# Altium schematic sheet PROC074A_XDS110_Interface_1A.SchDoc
size 431 x 279 mm; Date: Not shown in title block; ApprovedBy: Not shown in title block; CheckedBy: Not shown in title block; Author: Not shown in title block; CompanyName: Not shown in title block; Engineer: Not shown in title block; Organization: Not shown in title block; Address1: Not shown in title block; Address2: Not shown in title block; Address3: Not shown in title block; Address4: Not shown in title block; DocumentNumber: 1; Revision: Use project parameter SCH_Rev; SheetNumber: 11; SheetTotal: 22; PageSetup: Record=PageOptions¦CenterHorizontal=True¦CenterVertical=True¦PrintScale=1.00¦XCorrection=1.00¦YCorrection=1.00¦PrintKind=0¦BorderSize=5000000¦LeftOffset=0¦BottomOffset=0¦Orientation=2¦PaperLength=1000¦PaperWidth=1000¦Scale=100¦PaperSource=15¦PrintQuality=600¦MediaType=1¦DitherType=10¦PaperKind=Letter¦PrintScaleMode=1
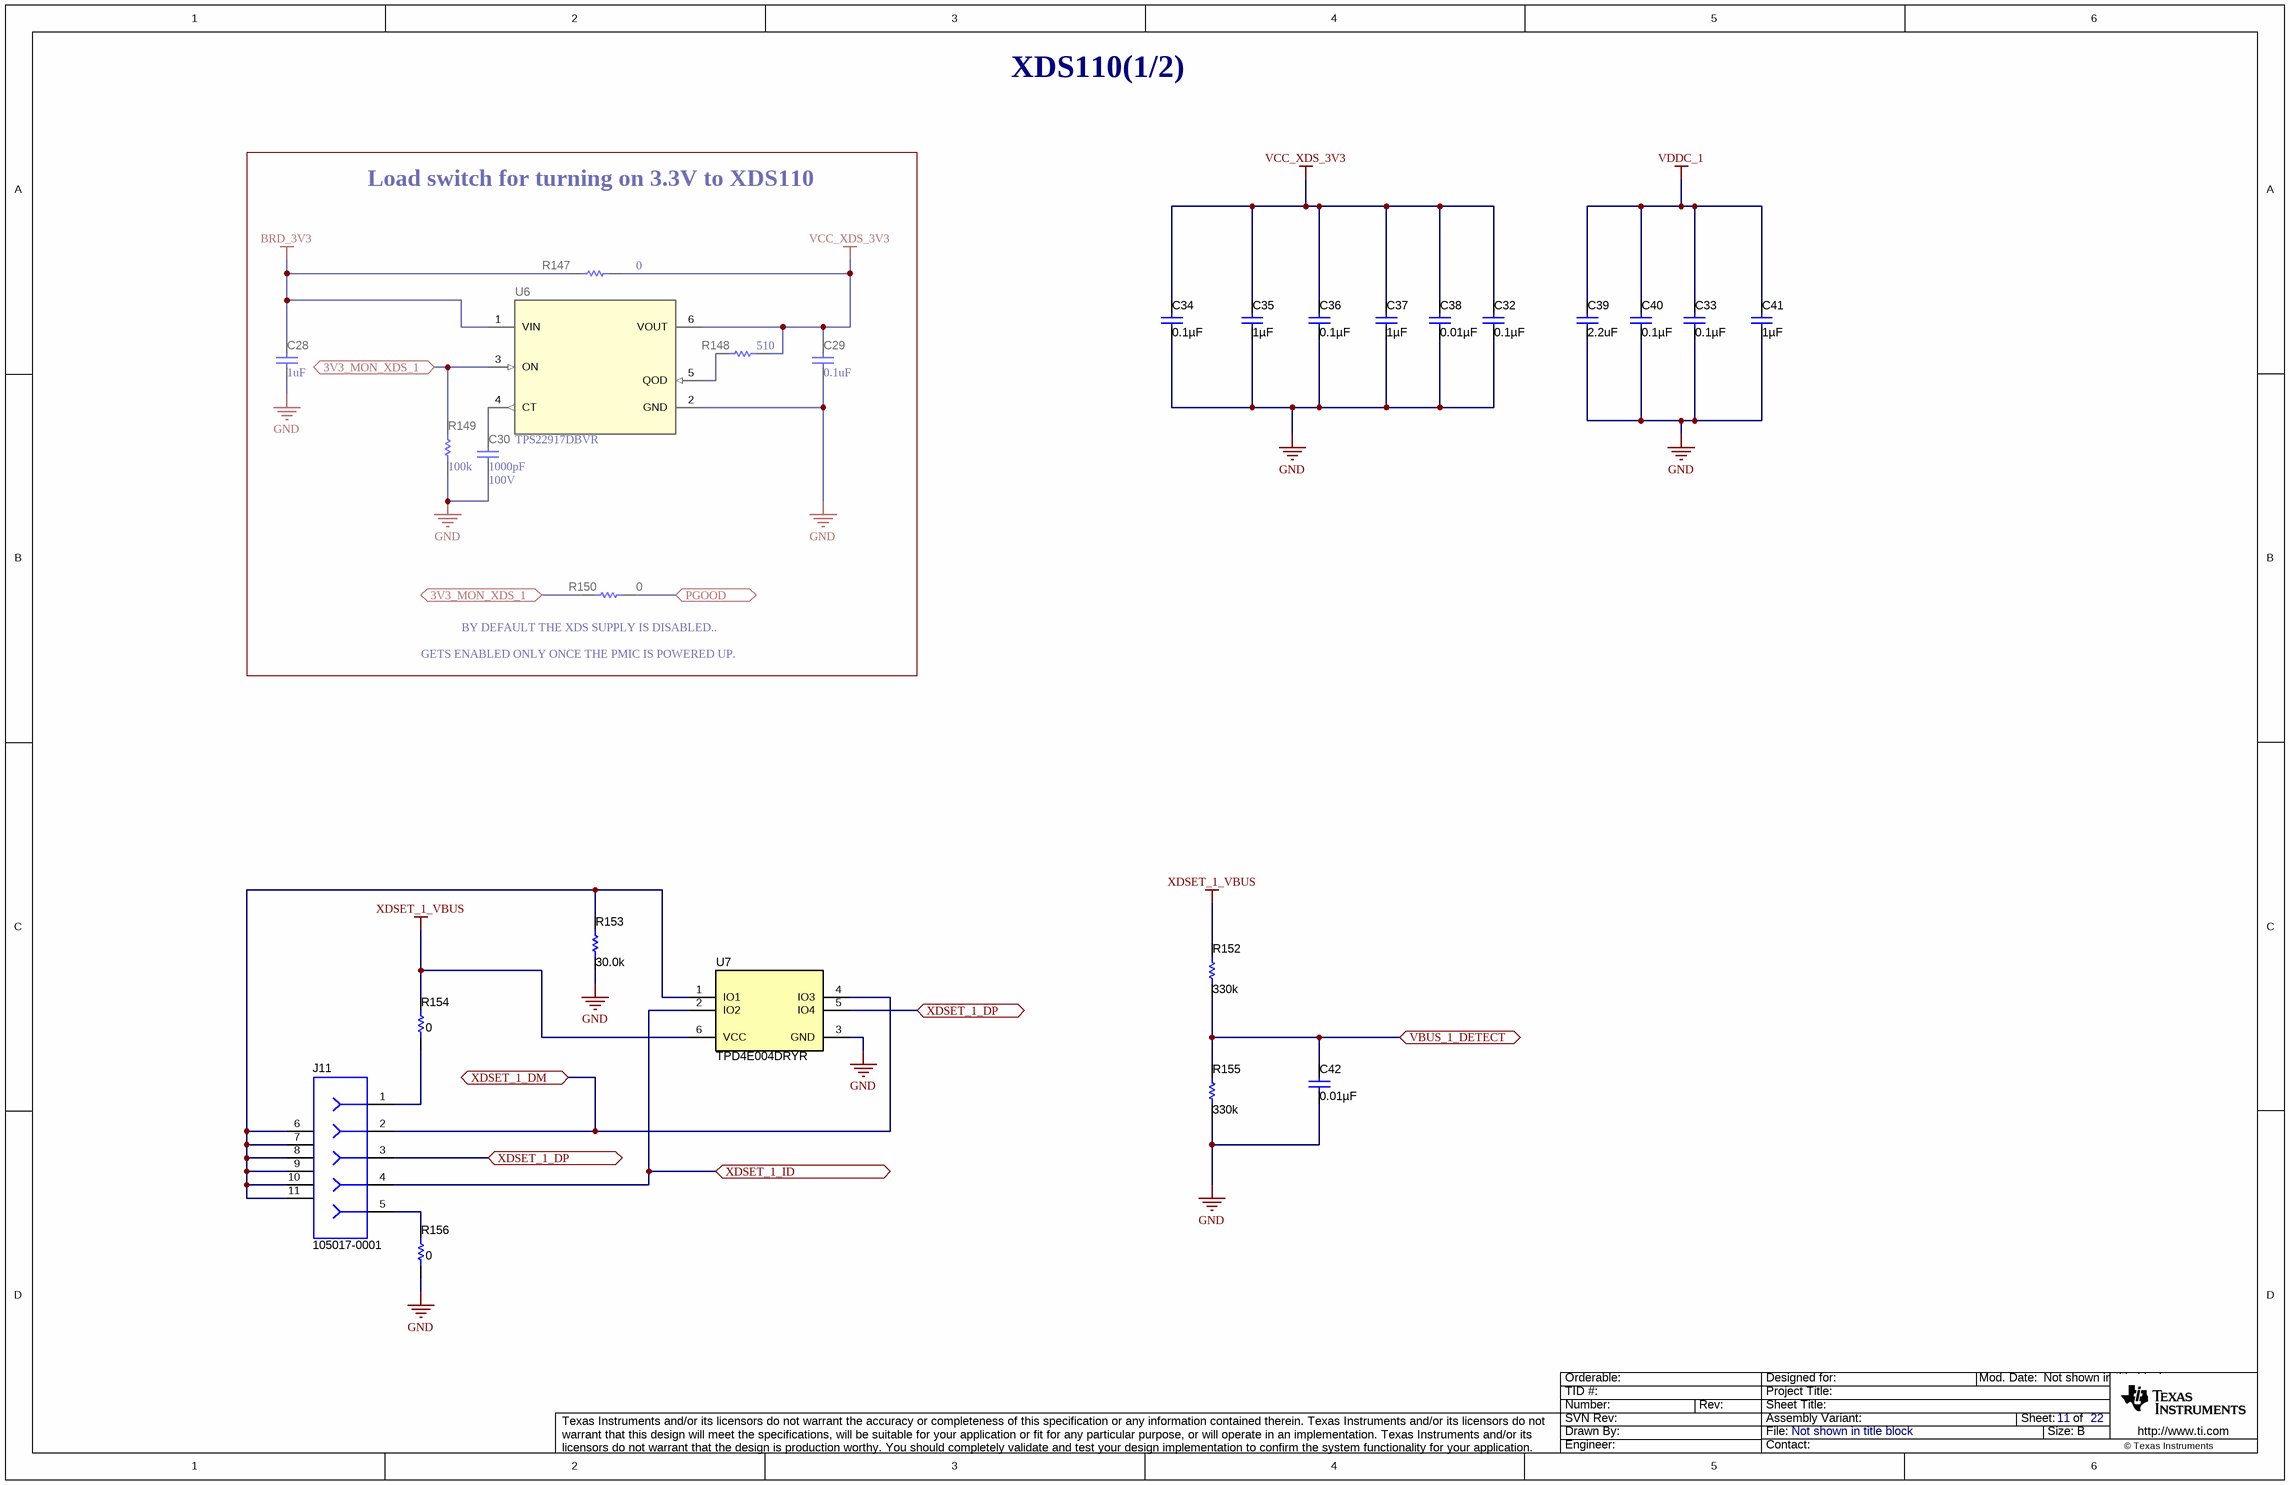
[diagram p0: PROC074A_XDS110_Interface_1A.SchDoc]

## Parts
C28  ValueDisplayed: 1uF  [0603]  (hidden comment: CL10B105KQ8NNNC)
C29  ValueDisplayed: 0.1uF  [0603]  (hidden comment: GRM188R70J104KA01D)
C30  VDC_V: 100V  ValueDisplayed: 1000pF  [0402]  (hidden comment: CGA2B3X7S2A102K050BB)
C32  ValueDisplayed: 0.1µF  [0402L]  (hidden comment: C0402C104K8RACTU)
C33  ValueDisplayed: 0.1µF  [0402L]  (hidden comment: C0402C104K8RACTU)
C34  ValueDisplayed: 0.1µF  [0402L]  (hidden comment: C0402C104K8RACTU)
C35  ValueDisplayed: 1µF  [0402L]  (hidden comment: C1005X7S0J105M050BC)
C36  ValueDisplayed: 0.1µF  [0402L]  (hidden comment: C0402C104K8RACTU)
C37  ValueDisplayed: 1µF  [0402L]  (hidden comment: C1005X7S0J105M050BC)
C38  ValueDisplayed: 0.01µF  [0402L]  (hidden comment: C1005X7R1E103K050BB)
C39  ValueDisplayed: 2.2uF  [0402_065L]  (hidden comment: C1005X7S1A225K050BC)
C40  ValueDisplayed: 0.1µF  [0402L]  (hidden comment: C0402C104K8RACTU)
C41  ValueDisplayed: 1µF  [0402L]  (hidden comment: C1005X7S0J105M050BC)
C42  ValueDisplayed: 0.01µF  [0402L]  (hidden comment: C0402C103K4RACTU)
J11  105017-0001  [CONN_105017-0001]
R147  ValueDisplayed: 0  [0603]  (hidden comment: RCS06030000Z0EA)
R148  ValueDisplayed: 510  [0402]  (hidden comment: CRCW0402510RJNED)
R149  ValueDisplayed: 100k  [0402]  (hidden comment: ERJ-2RKF1003X)
R150  ValueDisplayed: 0  [0402L]  (hidden comment: ERJ-2GE0R00X)
R152  ValueDisplayed: 330k  [0402L]  (hidden comment: CRCW0402330KFKED)
R153  ValueDisplayed: 30.0k  [0402L]  (hidden comment: CRCW040230K0FKED)
R154  ValueDisplayed: 0  [0603]  (hidden comment: MCT06030Z0000ZP500)
R155  ValueDisplayed: 330k  [0402L]  (hidden comment: CRCW0402330KFKED)
R156  ValueDisplayed: 0  [0603]  (hidden comment: MCT06030Z0000ZP500)
U6  TPS22917DBVR  [DBV0006A_L]
U7  TPD4E004DRYR  [DRY0006A]

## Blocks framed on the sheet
Load switch for turning on 3.3V to XDS110: C28-C30 R147-R150 U6

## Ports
3V3_MON_XDS_1, PGOOD, VBUS_1_DETECT, XDSET_1_DM, XDSET_1_DP, XDSET_1_ID

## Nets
BRD_3V3: C28.1 R147.1 U6.1(VIN)
GND: C28.2 C29.2 C30.2 C32.1 C33.1 C34.1 C35.1 C36.1 C37.1 C38.1 C39.1 C40.1 C41.1 C42.1 R149.1 R153.1 R155.1 R156.1 U6.2(GND) U7.3(GND)
VCC_XDS_3V3: C29.1 C32.2 C34.2 C35.2 C36.2 C37.2 C38.2 R147.2 R148.1 U6.6(VOUT)
VDDC_1: C33.2 C39.2 C40.2 C41.2
XDSET_1_VBUS: R152.2 R154.2 U7.6(VCC)
3V3_MON_XDS_1: R149.2 R150.2 U6.3(ON) ; port 3V3_MON_XDS_1
PGOOD: R150.1 ; port PGOOD
VBUS_1_DETECT: C42.2 R152.1 R155.2 ; port VBUS_1_DETECT
XDSET_1_DM: J11.2 U7.4(IO3) ; port XDSET_1_DM
XDSET_1_DP: J11.3 U7.5(IO4) ; port XDSET_1_DP
XDSET_1_ID: J11.4 U7.2(IO2) ; port XDSET_1_ID
NetC30_1: C30.1 U6.4(CT)
NetJ11_1: J11.1 R154.1
NetJ11_5: J11.5 R156.2
NetJ11_6: J11.6 J11.7 J11.8 J11.9 J11.10 J11.11 R153.2 U7.1(IO1)
NetR148_2: R148.2 U6.5(QOD)

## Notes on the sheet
- XDS110(1/2)
- (near R150) BY DEFAULT THE XDS SUPPLY IS DISABLED..
- GETS ENABLED ONLY ONCE THE PMIC IS POWERED UP.

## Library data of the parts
C28 = CMP-0007111-4: CAP, CERM, 1 uF, 6.3 V, +/- 10%, X7R, 0603; Manufacturer: Samsung Electro-Mechanics; TaMin_C: -55°C; Polarized: N; SizeAreaWB_mm2: 4.68; Value1: Unknown; U/M: EA; Value: 1uF; TaMax_C: 125°C; SizeZ_mm: 1; SizeX_mm: 1.6; SizeY_mm: 0.8; Value2: 6.3V; SizeArea_mm2: 1.28; CompType: Capacitor; Cap_F: 1µF; AEC Category: Q200
C29 = CMP-0007359-4: CAP, CERM, 0.1 uF, 6.3 V, +/- 10%, X7R, 0603; Manufacturer: MuRata; TaMin_C: -55°C; Polarized: N; SizeAreaWB_mm2: 4.68; Value1: Unknown; U/M: EA; Value: 0.1uF; TaMax_C: 125°C; SizeZ_mm: 1; SizeX_mm: 1.6; SizeY_mm: 0.8; Value2: 6.3V; SizeArea_mm2: 1.28; CompType: Capacitor; Cap_F: 100nF; AEC Category: Q200
C30 = CMP-0006332-2: CAP, CERM, 1000 pF, 100 V, +/- 10%, X7S, AEC-Q200 Grade 1, 0402; Manufacturer: TDK; TaMin_C: -55°C; ESR_ohm: 2.71151; Polarized: N; SizeAreaWB_mm2: 3; Value1: 2.71151 ohm; U/M: EA; Value: 1000pF; TaMax_C: 125°C; SizeZ_mm: 0.6; SizeX_mm: 1; SizeY_mm: 0.5; AEC Qualified: Y; Cap_F: 1nF; IRMS_A: 2.64589dA; AEC Category: Q200
C32-C34 C36 C40 = CMP-0078241-1: CAP, CERM, 0.1 µF, 10 V,+/- 10%, X7R, 0402; Manufacturer: Kemet; TaMin_C: -55°C; Polarized: N; SizeAreaWB_mm2: 3; U/M: EA; Value: 0.1uF; TaMax_C: 125°C; SizeZ_mm: 0.6; SizeX_mm: 1; SizeY_mm: 0.5; Cap_Case: 0402; Value2: 10V; CompType: Capacitor; Cap_F: 100nF; AEC Category: Q200
C35 C37 C41 = CMP-0078222-1: CAP, CERM, 1 µF, 6.3 V,+/- 20%, X7S, 0402; Manufacturer: TDK; TaMin_C: -55°C; Polarized: N; SizeAreaWB_mm2: 3; U/M: EA; Value: 1uF; TaMax_C: 125°C; SizeZ_mm: 0.6; SizeX_mm: 1; SizeY_mm: 0.5; Cap_Case: 0402; Value2: 6.3V; CompType: Capacitor; AEC Category: Q200
C38 = CMP-0078220-1: CAP, CERM, 0.01 µF, 25 V,+/- 10%, X7R, 0402; Manufacturer: TDK; TaMin_C: -55°C; Polarized: N; Green_Lifecycle: NRND; SizeAreaWB_mm2: 3; Green_REACh: Passed; U/M: EA; Value: 0.01uF; TaMax_C: 125°C; SizeZ_mm: 0.6; SizeX_mm: 1; SizeY_mm: 0.5; Cap_Case: 0402; Value2: 25V; CompType: Capacitor; Cap_F: 10nF; AEC Category: Q200
C39 = CMP-0006302-2: CAP, CERM, 2.2 uF, 10 V, +/- 10%, X7S, 0402; Manufacturer: TDK; TaMin_C: -55°C; ESR_ohm: 5.925m; Polarized: N; SizeAreaWB_mm2: 3; Value1: 0.005925 ohm; U/M: EA; Value: 2.2uF; TaMax_C: 125°C; SizeZ_mm: 0.65; SizeX_mm: 1; SizeY_mm: 0.5; Cap_Case: 0402_065; Value2: 10V; CompType: Capacitor; Cap_F: 2.2µF; IRMS_A: 2.05591A; AEC Category: Q200
C42 = CMP-0078218-1: CAP, CERM, 0.01 µF, 16 V,+/- 10%, X7R, 0402; Manufacturer: Kemet; TaMin_C: -55°C; Polarized: N; Green_Lifecycle: Active; SizeAreaWB_mm2: 3; Green_REACh: Passed; U/M: EA; Value: 0.01uF; TaMax_C: 125°C; SizeZ_mm: 0.6; SizeX_mm: 1; SizeY_mm: 0.5; Cap_Case: 0402; Value2: 16V; CompType: Capacitor; Cap_F: 10nF; AEC Category: Q200
J11 = CMP-0055293-1: Connector, Receptacle, Micro-USB Type B, R/A, Bottom Mount SMT; Manufacturer: Molex; CNHeader: FALSE; Green_Lifecycle: Active; Gender: Female; Green_REACh: Passed; CompType: USB; CT: TRUE
R147 = CMP-0081973-1: RES, 0, 0%, 0.25 W, AEC-Q200 Grade 0, 0603; Manufacturer: Vishay-Dale; SizeAreaWB_mm2: 4.68; SizeArea_mm2: 1.28; AEC Qualified: Y; AEC Category: Q200; Value: 0; SizeZ_mm: 1; SizeY_mm: 0.8; Power_W: 250mW; Value2: 0.25W; CompType: Resistor; SizeX_mm: 1.6; INSTALLATION: DNP
R148 = CMP-0026944-3: RES, 510, 5%, 0.063 W, AEC-Q200 Grade 0, 0402; Manufacturer: Vishay-Dale; Power_W: 63mW; TempCo: 200 ppm/C; Value_Code: 510R; Value: 510; EIA_Code: E24; SizeX_mm: 1; SizeY_mm: 0.5; SizeZ_mm: 0.6; Value2: 0.063W; AEC Qualified: Y; VDC_V: 50V; AEC Category: Q200; AEC Grade: 0
R149 = CMP-0026659-1: RES, 100 k, 1%, 0.1 W, 0402; Manufacturer: Panasonic; Power_W: 100mW; TempCo: 100 ppm/C; U/M: EA; Value: 100k; EIA_Code: E96; SizeX_mm: 1; SizeY_mm: 0.5; SizeZ_mm: 0.6; Value2: 0.1W; VDC_V: 50V; AEC Category: Q200
R150 = CMP-0026992-2: RES, 0, 5%, 0.063 W, 0402; Manufacturer: Panasonic; Power_W: 63mW; TempCo: 600 ppm/C; Value_Code: 0000; U/M: EA; Value: 0; EIA_Code: E24; SizeX_mm: 1; SizeY_mm: 0.5; SizeZ_mm: 0.6; Value2: 0.063W; VDC_V: 50V; AEC Category: Q200
R152 R155 = CMP-0078210-1: RES, 330 k, 1%, 0.063 W, AEC-Q200 Grade 0, 0402; Manufacturer: Vishay-Dale; SizeArea_mm2: 0.5; AEC Qualified: Y; AEC Category: Q200; Value: 330k; SizeZ_mm: 0.6; TempCo: 100 ppm/C; AEC Grade: 0; Power_W: 63mW; VDC_V: 50V; Value2: 0.063W; U/M: EA; SizeX_mm: 1
R153 = CMP-0078244-1: RES, 30.0 k, 1%, 0.063 W, AEC-Q200 Grade 0, 0402; Manufacturer: Vishay-Dale; Power_W: 63mW; Green_Lifecycle: Active; TempCo: 100 ppm/C; Value_Code: 30k0; Green_REACh: Passed; Value: 30.0k; Res_ohm: 30k; SizeX_mm: 1; SizeY_mm: 0.5; SizeZ_mm: 0.6; Value2: 0.063W; AEC Qualified: Y; VDC_V: 50V; AEC Grade: 0; AEC Category: Q200
R154 R156 = CMP-0025884-3: RES, 0, 5%, 0.125 W, 0603; Manufacturer: Vishay/Beyschlag; Power_W: 125mW; TempCo: ppm/C; Value_Code: 0000; U/M: EA; Value: 0; EIA_Code: E24; SizeX_mm: 1.6; SizeY_mm: 0.8; SizeZ_mm: 1; Value2: 0.125W; SizeArea_mm2: 1.28; AEC Qualified: N; AEC Category: Q200
U6 = CMP-0077265-1: 5.5-V, 2-A, 80 mohm Low Leakage Load Switch with RCB and Programmable Rise Time, DBV0006A (SOT-23-6); Alternate PartNumber: TPS22917DBVT; Alternate Manufacturer: Texas Instruments; SizeAreaWB_mm2: 14.82; SizeZ_mm: 1.45; SizeX_mm: 2.8; SizeY_mm: 2.9; SizeArea_mm2: 8.12; CompType: IC; AEC Qualified: N; AEC Category: Q200
U7 = CMP-0043115-1: ESD-Protection Array for High-Speed Data Interfaces, 4 Channels, -40 to +85 degC, 6-pin SON (DRY), Green (RoHS & no Sb/Br); Manufacturer: Texas Instruments; IO Leakage Current(nA): 1; USB High Speed: TRUE; IO Capacitance(Typ)(pF): 1.6; SubFamily: ESD Solution; IEC 61000-4-2 Contact(+/- kV): 8; Breakdown Voltage(Min)(V): 6; IEC 61000-4-2 Air-Gap(+/- kV): 12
